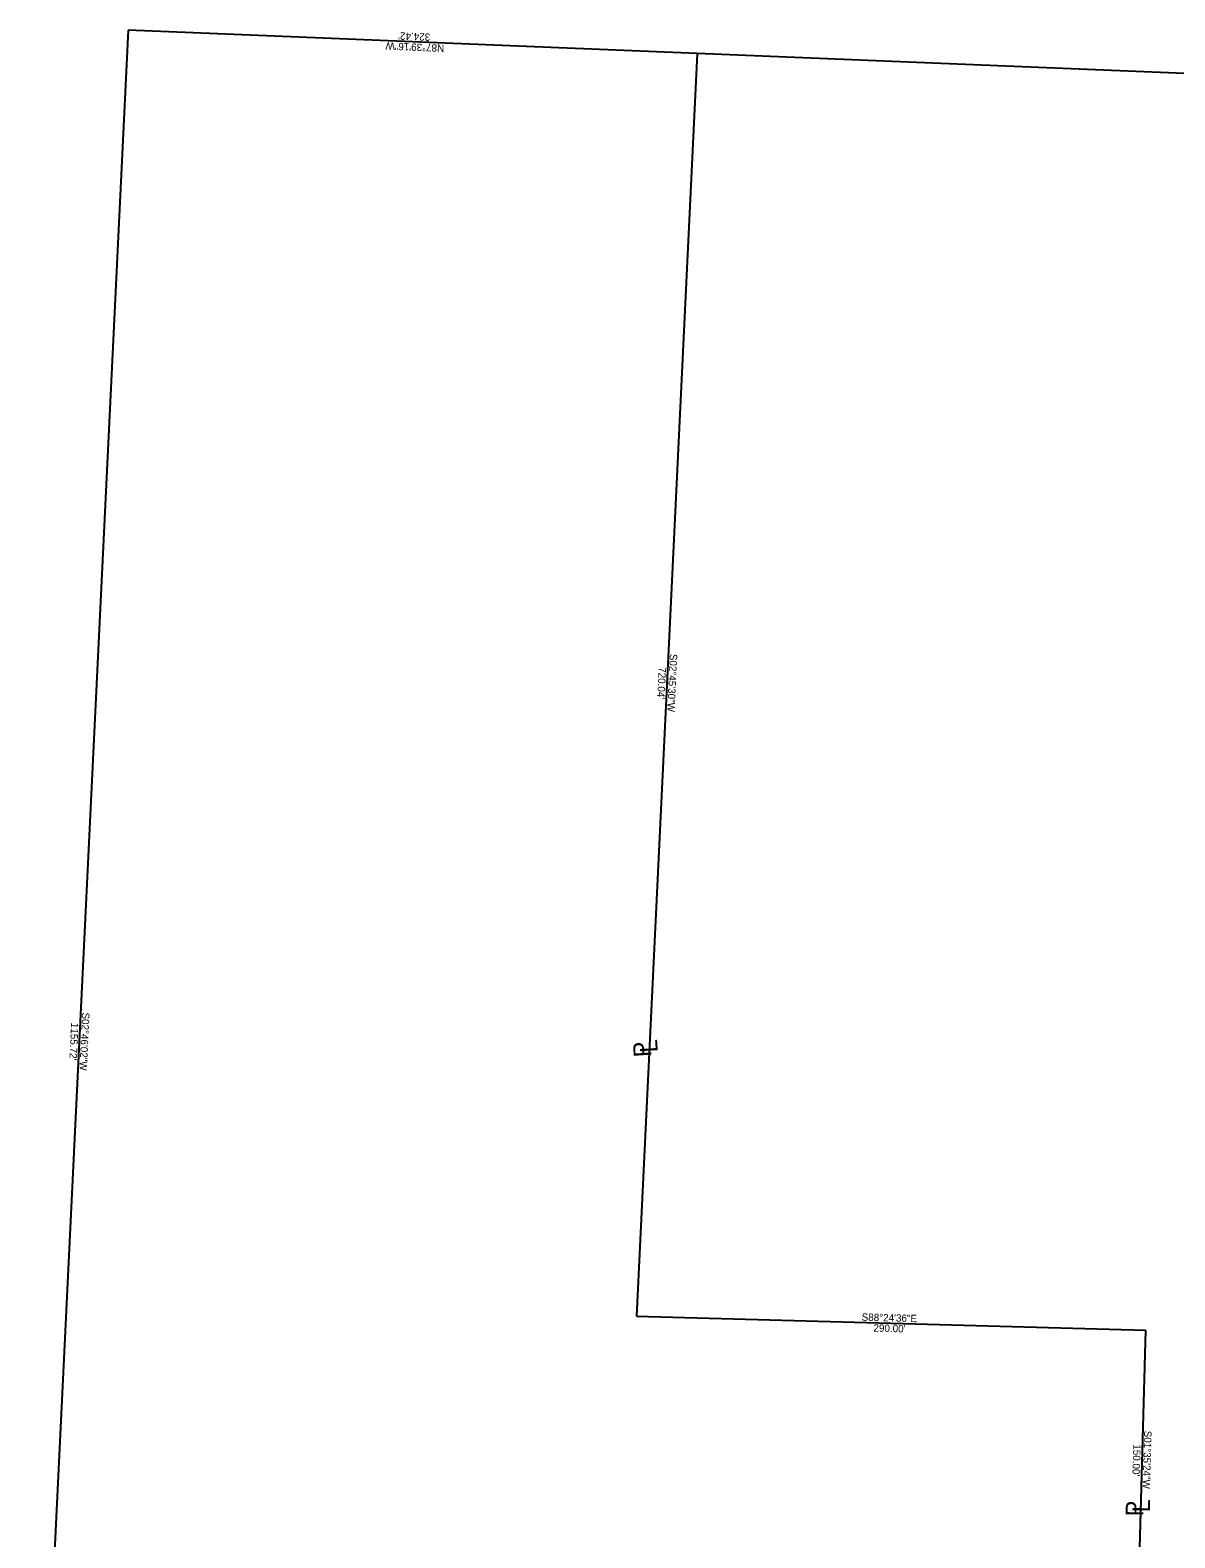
# Model space of a CAD drawing. Extents: x 1145508 to 2262867, y -3126236 to 2021677.
# Drawn here: x 1150390 to 1151042, y 2020678 to 2021537 of the extents above; entities that cross this region are included whole.
import ezdxf

# ---------------------------------------------------------------- set-up
doc = ezdxf.new("R2010")
doc.units = 0
for name, color, linetype in [('DSN_ROW_Annotation', 7, 'Continuous'), ('DSN_ROW_Prop-Line', 7, 'Continuous'), ('DSN_ROW_Prop-Line-Annotation', 7, 'Continuous'), ('EX_QSECTION', 7, 'Continuous'), ('EX_ROW_ANNOT', 7, 'Continuous'), ('EX_SECTION', 7, 'Continuous')]:
    doc.layers.add(name, color=color, linetype=linetype)

msp = doc.modelspace()

# ---------------------------------------------------------------- linework, layer by layer
at = {"layer": 'DSN_ROW_Prop-Line'}
for p, q in [((1150770.2, 2021523.67), (1150735.55, 2020804.46)), ((1150735.55, 2020804.46), (1151025.44, 2020796.42)), ((1151025.44, 2020796.42), (1151021.27, 2020646.48))]:
    msp.add_line(p, q, dxfattribs=at)
at = {"layer": 'EX_QSECTION'}
msp.add_line((1150446.06, 2021536.95), (1150390.26, 2020382.58), dxfattribs=at)
at = {"layer": 'EX_SECTION'}
for p, q in [((1150770.2, 2021523.67), (1150446.06, 2021536.95)), ((1151764.37, 2021482.95), (1150770.2, 2021523.67))]:
    msp.add_line(p, q, dxfattribs=at)

# ---------------------------------------------------------------- texts
at = {"layer": 'DSN_ROW_Annotation'}
for s, rotation, p in [('S02°45\'30"W', 267.24153, (1150754.63, 2021181.77)), ("720.04'", 267.24153, (1150748.25, 2021174.16)), ('S88°24\'36"E', 358.41012, (1150863.76, 2020801.81)), ("290.00'", 358.41012, (1150870.5, 2020795.62)), ('S01°35\'24"W', 268.41012, (1151024.75, 2020739.19)), ("150.00'", 268.41012, (1151018.53, 2020731.44))]:
    msp.add_text(s, height=4.2, rotation=rotation, dxfattribs=at).set_placement(p)
at = {"layer": 'DSN_ROW_Prop-Line-Annotation'}
for s, rotation, p in [('P', 93.78824, (1150744.08, 2020952.27)), ('L', 93.78824, (1150747.75, 2020954.85)), ('P', 89.6142, (1151024.21, 2020690.34)), ('L', 89.6142, (1151028.06, 2020692.64))]:
    msp.add_text(s, height=10, rotation=rotation, dxfattribs=at).set_placement(p)
at = {"layer": 'EX_ROW_ANNOT'}
for s, rotation, p in [("324.42'", 177.65453, (1150618.18, 2021535)), ("324.42'", 177.65453, (1150618.18, 2021535)), ('N87°39\'16"W', 177.65453, (1150626.14, 2021528.67)), ('N87°39\'16"W', 177.65453, (1150626.14, 2021528.67)), ('S02°46\'02"W', 267.2328, (1150419.91, 2020977.47)), ('S02°46\'02"W', 267.2328, (1150419.91, 2020977.47)), ("1155.72'", 267.2328, (1150413.62, 2020971.56)), ("1155.72'", 267.2328, (1150413.62, 2020971.56))]:
    msp.add_text(s, height=4.2, rotation=rotation, dxfattribs=at).set_placement(p)

doc.saveas('drawing.dxf')
